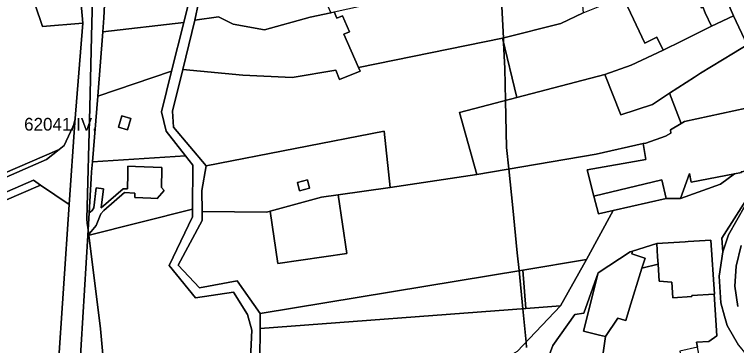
# Model space of a CAD drawing. Extents: x -522079 to -518833, y -1142400 to -1139961.
# Drawn here: x -520623.1 to -520338.9, y -1141173.1 to -1141042.9 of the extents above; entities that cross this region are included whole.
import ezdxf

# ---------------------------------------------------------------- set-up
doc = ezdxf.new("R2010")
doc.units = 0
for name, color, linetype in [('95590013', 7, 'Continuous'), ('95610013', 7, 'Continuous'), ('95620013', 7, 'Continuous'), ('95630013', 7, 'Continuous'), ('95640013', 7, 'Continuous'), ('95660013', 7, 'Continuous')]:
    doc.layers.add(name, color=color, linetype=linetype)

msp = doc.modelspace()

# ---------------------------------------------------------------- linework, layer by layer
at = {"layer": '95590013'}
for points in [[(-520620.51, -1141022.34), (-520648.03, -1140963.9), (-520600.24, -1140966.98), (-520604.67, -1140967.12), (-520604.41, -1140978.31), (-520604.3, -1140983.07), (-520599.81, -1140983.06), (-520599.73, -1140986.18), (-520599.09, -1141003), (-520600.97, -1141003.07), (-520601.06, -1141001.34), (-520601.36, -1141001.34), (-520602.52, -1141000.7), (-520603.99, -1141000.76), (-520605.04, -1141001.54), (-520605.37, -1141001.56), (-520605.29, -1141003.25), (-520607.09, -1141003.32), (-520615.08, -1141003.61), (-520614.42, -1141021.92), (-520598.37, -1141020.83), (-520596.21, -1141046.3), (-520612.04, -1141047.58)], [(-520400.21, -1141032.13), (-520399.24, -1141042.3), (-520408.06, -1141046.45), (-520431.05, -1141052.26), (-520487.67, -1141063.72), (-520493.42, -1141050.65), (-520491.27, -1141049.7), (-520494.03, -1141043.4), (-520496.2, -1141044.35), (-520497.24, -1141041.88), (-520452.37, -1141031.92), (-520412.3, -1141020.92), (-520402.65, -1141017.41), (-520392.22, -1141014.66), (-520391.74, -1141015.46), (-520389.08, -1141019.93), (-520401.32, -1141023.68), (-520401.95, -1141022.11), (-520410.31, -1141025.45), (-520406.62, -1141034.69)], [(-520552.06, -1141045.13), (-520547.82, -1141024.57), (-520531.57, -1141026.89), (-520508.38, -1141020.64), (-520498.56, -1141042.19), (-520506.76, -1141043.95), (-520524.68, -1141048.94), (-520537, -1141046.7), (-520542.8, -1141043.78)], [(-520487.08, -1141065.15), (-520495.15, -1141068.52), (-520496.65, -1141064.79), (-520513.82, -1141067.62), (-520533.21, -1141066.79), (-520556.84, -1141064.48), (-520552.06, -1141045.13), (-520542.8, -1141043.78), (-520537, -1141046.7), (-520524.68, -1141048.94), (-520506.76, -1141043.95), (-520498.56, -1141042.19), (-520497.24, -1141041.88), (-520496.2, -1141044.35), (-520494.03, -1141043.4), (-520491.27, -1141049.7), (-520493.42, -1141050.65), (-520487.67, -1141063.72)], [(-520561.24, -1141065.24), (-520590.32, -1141074.97), (-520588.29, -1141049.68), (-520556.5, -1141046.1)], [(-520487.67, -1141063.72), (-520431.05, -1141052.26), (-520425.4, -1141075.5), (-520447.94, -1141081.43), (-520441.13, -1141105.78), (-520475.18, -1141110.92), (-520477.6, -1141088.85), (-520547.68, -1141102.49), (-520560.53, -1141087.18), (-520560.89, -1141080.93), (-520556.84, -1141064.48), (-520533.21, -1141066.79), (-520513.82, -1141067.62), (-520496.65, -1141064.79), (-520495.15, -1141068.52), (-520487.08, -1141065.15)], [(-520375.66, -1141093.7), (-520394.23, -1141097.85), (-520441.13, -1141105.78), (-520447.94, -1141081.43), (-520425.4, -1141075.5), (-520390.79, -1141066.51), (-520384.48, -1141082.4), (-520371.97, -1141078.27), (-520365.3, -1141073.88), (-520360.71, -1141085.77), (-520364.98, -1141088.31), (-520364.74, -1141089.55), (-520366.94, -1141090.81), (-520374.62, -1141093.47)], [(-520495.67, -1141113.78), (-520502.3, -1141114.71), (-520522.42, -1141120.25), (-520523.74, -1141120.61), (-520549.23, -1141120.44), (-520549.29, -1141112.12), (-520547.68, -1141102.49), (-520477.6, -1141088.85), (-520475.18, -1141110.92)], [(-520492.31, -1141136.96), (-520495.67, -1141113.78), (-520475.18, -1141110.92), (-520441.13, -1141105.78), (-520394.23, -1141097.85), (-520375.66, -1141093.7), (-520374.68, -1141099.98), (-520397.79, -1141103.97), (-520395.09, -1141114.42), (-520393.3, -1141121.36), (-520387.46, -1141120.02), (-520397.97, -1141139.24), (-520423.06, -1141143.4), (-520526.34, -1141160.53), (-520535.5, -1141147.72), (-520550.27, -1141150.4), (-520558.62, -1141141.55), (-520549.21, -1141123.97), (-520549.23, -1141120.44), (-520523.74, -1141120.61), (-520522.42, -1141120.25), (-520519.42, -1141140.9)], [(-520552.84, -1141102.13), (-520552.98, -1141119.42), (-520594.25, -1141129.86), (-520590.98, -1141125.93), (-520589.1, -1141121.25), (-520587.97, -1141120.05), (-520579.73, -1141112.98), (-520575.7, -1141113.22), (-520575.71, -1141114.91), (-520569.44, -1141115.09), (-520566.93, -1141115.3), (-520564.14, -1141112.07), (-520565.25, -1141110.92), (-520565.05, -1141103.74), (-520565.03, -1141103.04), (-520575.39, -1141102.74), (-520578.44, -1141102.51), (-520578.5, -1141105.52), (-520578.63, -1141111.5), (-520580.29, -1141111.47), (-520588.95, -1141118.89), (-520588.02, -1141111.45), (-520590.95, -1141111.08), (-520591.88, -1141118.95), (-520592.5, -1141120.04), (-520593.72, -1141120.93), (-520592.91, -1141107.42), (-520592.76, -1141104.85), (-520592.43, -1141100.83), (-520555.74, -1141098.46)], [(-520345.24, -1141109.63), (-520361.02, -1141115.3), (-520357.5, -1141105.49), (-520356.84, -1141108.9), (-520339.78, -1141105.62)], [(-520506.98, -1141111.26), (-520507.81, -1141107.97), (-520511.72, -1141108.95), (-520510.88, -1141112.27)], [(-520393.3, -1141121.36), (-520395.09, -1141114.42), (-520368.35, -1141107.89), (-520366.58, -1141115.24), (-520387.46, -1141120.02)], [(-520522.42, -1141120.25), (-520502.3, -1141114.71), (-520495.67, -1141113.78), (-520492.31, -1141136.96), (-520519.42, -1141140.9)], [(-520374.94, -1141138.7), (-520375.42, -1141138.55), (-520380.21, -1141137.08), (-520379.87, -1141135.97), (-520370.32, -1141133), (-520369.99, -1141138.16), (-520369.8, -1141141.08), (-520376.18, -1141142.7)], [(-520526.38, -1141166.45), (-520526.34, -1141160.53), (-520423.06, -1141143.4), (-520421.91, -1141158.52)], [(-520392.71, -1141184.99), (-520390.51, -1141169.6), (-520385.67, -1141162.39), (-520383.02, -1141163.15), (-520382.54, -1141163.3), (-520381.05, -1141158.47), (-520376.18, -1141142.7), (-520369.8, -1141141.08), (-520369.36, -1141147.79), (-520364.41, -1141148.17), (-520363.98, -1141154.29), (-520356.57, -1141153.77), (-520356.59, -1141153.47), (-520347.81, -1141152.92), (-520346.65, -1141169.3), (-520349.86, -1141171.48), (-520354.71, -1141171.83), (-520354.34, -1141173.71), (-520361.25, -1141175.35), (-520360.34, -1141179.18), (-520366.93, -1141180.34), (-520378.86, -1141182.41)], [(-520417.36, -1141189.63), (-520411.3, -1141173.03), (-520402.63, -1141160.92), (-520399.1, -1141160.34), (-520393.37, -1141144.49), (-520399.12, -1141167.44), (-520392.92, -1141168.99), (-520390.51, -1141169.6), (-520392.71, -1141184.99)]]:
    msp.add_lwpolyline(points, close=True, dxfattribs=at)
at = {"layer": '95610013'}
for points in [[(-520679.92, -1141124.76), (-520699.09, -1140943.92), (-520632.04, -1140920.85), (-520634.37, -1140902.81), (-520641.23, -1140863.72), (-520646.19, -1140843.58), (-520650.7, -1140826.31), (-520634.79, -1140817.77), (-520621.9, -1140866.86), (-520618.56, -1140880.81), (-520614.37, -1140907.34), (-520612.5, -1140933.48), (-520590.36, -1140946.34), (-520594.75, -1140964.79), (-520649.51, -1140960.76), (-520648.03, -1140963.9), (-520620.51, -1141022.34), (-520612.04, -1141047.58), (-520596.21, -1141046.3), (-520599.33, -1141085.41), (-520603.47, -1141094.45), (-520605.48, -1141096), (-520676.95, -1141126.77)], [(-520586.99, -1141025.98), (-520551.07, -1141024.16), (-520556.5, -1141046.1), (-520588.29, -1141049.68), (-520587.85, -1141044.25)], [(-520565.18, -1141081.15), (-520563.4, -1141088.78), (-520555.74, -1141098.46), (-520592.43, -1141100.83), (-520590.32, -1141074.97), (-520561.24, -1141065.24)], [(-520582.09, -1141087.24), (-520578.55, -1141088.26), (-520577.31, -1141083.78), (-520580.82, -1141082.81)], [(-520597.46, -1141183.55), (-520594.25, -1141129.86), (-520552.98, -1141119.42), (-520553, -1141122.43), (-520562.26, -1141141.67), (-520551.87, -1141154.33), (-520536.94, -1141152.14), (-520531.44, -1141160.96), (-520529.73, -1141167.05), (-520530.26, -1141178.39), (-520534.49, -1141178.34), (-520588.63, -1141182.42)], [(-520432.59, -1141179.7), (-520440.68, -1141181.04), (-520523.78, -1141178.47), (-520526.48, -1141178.44), (-520526.38, -1141166.45), (-520421.91, -1141158.52), (-520408.18, -1141157.48), (-520425.27, -1141175.41)]]:
    msp.add_lwpolyline(points, close=True, dxfattribs=at)
at = {"layer": '95620013'}
msp.add_lwpolyline([(-520607.02, -1141187.64), (-520665.65, -1141273.94), (-520677.78, -1141138.02), (-520612.8, -1141110.04), (-520601.54, -1141117.64), (-520606.07, -1141183.78)], close=True, dxfattribs=at)
at = {"layer": '95630013'}
for points in [[(-520530.26, -1141178.39), (-520529.73, -1141167.05), (-520531.44, -1141160.96), (-520536.94, -1141152.14), (-520551.87, -1141154.33), (-520562.26, -1141141.67), (-520553, -1141122.43), (-520552.98, -1141119.42), (-520552.84, -1141102.13), (-520555.74, -1141098.46), (-520563.4, -1141088.78), (-520565.18, -1141081.15), (-520561.24, -1141065.24), (-520556.5, -1141046.1), (-520551.07, -1141024.16)], [(-520547.82, -1141024.57), (-520552.06, -1141045.13), (-520556.84, -1141064.48), (-520560.89, -1141080.93), (-520560.53, -1141087.18), (-520547.68, -1141102.49), (-520549.29, -1141112.12), (-520549.23, -1141120.44), (-520549.21, -1141123.97), (-520558.62, -1141141.55), (-520550.27, -1141150.4), (-520535.5, -1141147.72), (-520526.34, -1141160.53), (-520526.38, -1141166.45), (-520526.48, -1141178.44)]]:
    msp.add_lwpolyline(points, dxfattribs=at)
at = {"layer": '95640013'}
for points in [[(-520334.74, -1141054.84), (-520340.18, -1141043.47), (-520343.25, -1141036.1), (-520347.88, -1141025.34), (-520350.1, -1141020.17), (-520349.61, -1141019.9), (-520359.98, -1141000.07), (-520369.44, -1140980.74), (-520376.07, -1140958.44), (-520381.51, -1140937.64), (-520383.27, -1140930.85), (-520385, -1140920.46), (-520387.91, -1140902.86), (-520388.38, -1140878.81), (-520385.81, -1140848.46), (-520386.02, -1140848.4), (-520386.88, -1140823.39), (-520383.07, -1140848.38), (-520382.78, -1140878.64), (-520380.96, -1140902.07), (-520377.25, -1140930.57), (-520371.53, -1140953.82), (-520335.76, -1141038.73)], [(-520606.07, -1141183.78), (-520601.54, -1141117.64), (-520599.33, -1141085.41), (-520596.21, -1141046.3), (-520598.37, -1141020.83)], [(-520586.99, -1141025.98), (-520587.85, -1141044.25), (-520588.29, -1141049.68), (-520590.32, -1141074.97), (-520592.43, -1141100.83), (-520592.76, -1141104.85), (-520592.91, -1141107.42), (-520593.72, -1141120.93), (-520594.25, -1141129.86), (-520597.46, -1141183.55)], [(-521027.41, -1141281.92), (-520897.83, -1141225.78), (-520885.55, -1141220.5), (-520708.05, -1141142.54), (-520688.68, -1141134.03), (-520675.02, -1141128.07), (-520610.52, -1141099.9), (-520605.48, -1141096), (-520603.47, -1141094.45), (-520599.33, -1141085.41), (-520601.54, -1141117.64), (-520612.8, -1141110.04), (-520615.64, -1141108.13), (-520683.34, -1141137.56), (-520705.75, -1141147.3), (-520882.39, -1141224.1), (-520895.38, -1141229.74), (-521025.25, -1141286.2)], [(-520425.27, -1141175.41), (-520408.18, -1141157.48), (-520397.97, -1141139.24), (-520387.46, -1141120.02), (-520366.58, -1141115.24), (-520361.02, -1141115.3), (-520345.24, -1141109.63), (-520339.78, -1141105.62), (-520337.04, -1141105.09), (-520337.09, -1141104.85), (-520328.09, -1141103.27), (-520327.42, -1141103.8), (-520344.78, -1141130.88), (-520344.38, -1141136.25), (-520345.84, -1141145.82), (-520345.14, -1141156.25), (-520343.69, -1141161.58), (-520342.68, -1141165.24), (-520338.22, -1141172.95), (-520335.19, -1141176.69)], [(-520335.59, -1141118), (-520342.14, -1141129.51), (-520344.38, -1141136.25), (-520344.78, -1141130.88), (-520327.42, -1141103.8)], [(-520338.22, -1141172.95), (-520342.68, -1141165.24), (-520343.69, -1141161.58), (-520345.14, -1141156.25), (-520345.84, -1141145.82), (-520344.38, -1141136.25), (-520342.14, -1141129.51), (-520335.59, -1141118)], [(-520337.15, -1141133.73), (-520339.09, -1141141.84), (-520339.64, -1141149.76), (-520338.41, -1141157.75)], [(-520338.41, -1141157.75), (-520339.64, -1141149.76), (-520339.09, -1141141.84), (-520337.15, -1141133.73)]]:
    msp.add_lwpolyline(points, dxfattribs=at)
for points in [[(-520367.77, -1141056.92), (-520370.31, -1141051.82), (-520375, -1141054.13), (-520382.96, -1141037.48), (-520379.56, -1141036.01), (-520380, -1141035.01), (-520357.91, -1141024.53), (-520350.1, -1141020.17), (-520347.88, -1141025.34), (-520357.55, -1141029.54), (-520352.93, -1141040.25), (-520352.22, -1141039.94), (-520351.25, -1141042.23), (-520348.84, -1141047.55), (-520360.31, -1141053.23)], [(-520375, -1141054.13), (-520370.31, -1141051.82), (-520367.77, -1141056.92), (-520380.42, -1141062.83), (-520390.79, -1141066.51), (-520425.4, -1141075.5), (-520431.05, -1141052.26), (-520408.06, -1141046.45), (-520399.24, -1141042.3), (-520385.48, -1141036.63), (-520380.26, -1141034.58), (-520380, -1141035.01), (-520379.56, -1141036.01), (-520382.96, -1141037.48)], [(-520352.22, -1141039.94), (-520343.25, -1141036.1), (-520340.18, -1141043.47), (-520348.84, -1141047.55), (-520351.25, -1141042.23)], [(-520348.84, -1141047.55), (-520340.18, -1141043.47), (-520334.74, -1141054.84), (-520340.14, -1141058.06), (-520353.1, -1141065.99), (-520355.55, -1141067.49), (-520365.3, -1141073.88), (-520371.97, -1141078.27), (-520384.48, -1141082.4), (-520390.79, -1141066.51), (-520380.42, -1141062.83), (-520367.77, -1141056.92), (-520360.31, -1141053.23)], [(-520334.74, -1141054.84), (-520329.51, -1141066.36), (-520330.22, -1141066.74), (-520330.35, -1141078.64), (-520359.41, -1141084.99), (-520360.71, -1141085.77), (-520365.3, -1141073.88), (-520355.55, -1141067.49), (-520353.1, -1141065.99), (-520340.14, -1141058.06)], [(-520374.68, -1141099.98), (-520375.66, -1141093.7), (-520374.62, -1141093.47), (-520366.94, -1141090.81), (-520364.74, -1141089.55), (-520364.98, -1141088.31), (-520360.71, -1141085.77), (-520359.41, -1141084.99), (-520330.35, -1141078.64), (-520328.09, -1141103.27), (-520337.09, -1141104.85), (-520337.04, -1141105.09), (-520339.78, -1141105.62), (-520356.84, -1141108.9), (-520357.5, -1141105.49), (-520361.02, -1141115.3), (-520366.58, -1141115.24), (-520368.35, -1141107.89), (-520395.09, -1141114.42), (-520397.79, -1141103.97)], [(-520582.09, -1141087.24), (-520580.82, -1141082.81), (-520577.31, -1141083.78), (-520578.55, -1141088.26)], [(-520676.95, -1141126.77), (-520605.48, -1141096), (-520610.52, -1141099.9), (-520675.02, -1141128.07)], [(-520565.25, -1141110.92), (-520564.14, -1141112.07), (-520566.93, -1141115.3), (-520569.44, -1141115.09), (-520575.71, -1141114.91), (-520575.7, -1141113.22), (-520579.73, -1141112.98), (-520587.97, -1141120.05), (-520589.1, -1141121.25), (-520590.98, -1141125.93), (-520594.25, -1141129.86), (-520593.72, -1141120.93), (-520592.5, -1141120.04), (-520591.88, -1141118.95), (-520590.95, -1141111.08), (-520588.02, -1141111.45), (-520588.95, -1141118.89), (-520580.29, -1141111.47), (-520578.63, -1141111.5), (-520578.5, -1141105.52), (-520578.44, -1141102.51), (-520575.39, -1141102.74), (-520565.03, -1141103.04), (-520565.05, -1141103.74)], [(-520615.64, -1141108.13), (-520612.8, -1141110.04), (-520677.78, -1141138.02), (-520683.09, -1141140.3), (-520683.34, -1141137.56)], [(-520510.88, -1141112.27), (-520511.72, -1141108.95), (-520507.81, -1141107.97), (-520506.98, -1141111.26)], [(-520417.36, -1141189.63), (-520392.71, -1141184.99), (-520378.86, -1141182.41), (-520366.93, -1141180.34), (-520360.34, -1141179.18), (-520353.47, -1141177.71), (-520354.34, -1141173.71), (-520354.71, -1141171.83), (-520349.86, -1141171.48), (-520346.65, -1141169.3), (-520347.81, -1141152.92), (-520347.61, -1141152.91), (-520349.11, -1141131.64), (-520357.95, -1141132.21), (-520359.15, -1141132.28), (-520370.32, -1141133), (-520379.87, -1141135.97), (-520380.82, -1141136.27), (-520393.37, -1141144.49), (-520399.1, -1141160.34), (-520402.63, -1141160.92), (-520411.3, -1141173.03)], [(-520357.95, -1141132.21), (-520349.11, -1141131.64), (-520347.61, -1141152.91), (-520347.81, -1141152.92), (-520356.59, -1141153.47), (-520356.57, -1141153.77), (-520363.98, -1141154.29), (-520364.41, -1141148.17), (-520369.36, -1141147.79), (-520369.8, -1141141.08), (-520369.99, -1141138.16), (-520370.32, -1141133), (-520359.15, -1141132.28)], [(-520379.87, -1141135.97), (-520380.21, -1141137.08), (-520375.42, -1141138.55), (-520374.94, -1141138.7), (-520376.18, -1141142.7), (-520381.05, -1141158.47), (-520382.54, -1141163.3), (-520383.02, -1141163.15), (-520385.67, -1141162.39), (-520390.51, -1141169.6), (-520392.92, -1141168.99), (-520399.12, -1141167.44), (-520393.37, -1141144.49), (-520380.82, -1141136.27)], [(-520421.91, -1141158.52), (-520423.06, -1141143.4), (-520397.97, -1141139.24), (-520408.18, -1141157.48)]]:
    msp.add_lwpolyline(points, close=True, dxfattribs=at)
at = {"layer": '95660013'}
for points in [[(-520627.56, -1140949.7), (-520621.19, -1140951.83), (-520619.9, -1140953.77), (-520618, -1140956.63), (-520614.03, -1140963.37), (-520612.45, -1140966.05), (-520611.1, -1140968.35), (-520603.66, -1140990.19), (-520600.09, -1141003.03), (-520598.92, -1141007.25), (-520592.23, -1141031.31), (-520592.74, -1141051.53), (-520593.45, -1141079.44), (-520594.66, -1141123.3), (-520594.45, -1141124.94), (-520594.12, -1141127.62), (-520593.85, -1141129.76), (-520589.2, -1141166.56), (-520587.79, -1141182.35)], [(-520587.79, -1141182.35), (-520589.2, -1141166.56), (-520593.85, -1141129.76), (-520594.12, -1141127.62), (-520594.45, -1141124.94), (-520594.66, -1141123.3), (-520593.45, -1141079.44), (-520592.74, -1141051.53), (-520592.23, -1141031.31)], [(-520421.57, -1141173.87), (-520421.78, -1141171.75), (-520423.07, -1141158.61), (-520424.53, -1141143.64), (-520425.21, -1141136.71), (-520427.04, -1141118.9), (-520428.61, -1141103.66), (-520429.47, -1141095.28), (-520429.83, -1141076.67), (-520430.07, -1141064.2), (-520430.6, -1141054.09), (-520430.7, -1141052.17), (-520431.36, -1141039.71)], [(-520431.36, -1141039.71), (-520430.7, -1141052.17), (-520430.6, -1141054.09), (-520430.07, -1141064.2), (-520429.83, -1141076.67), (-520429.47, -1141095.28), (-520428.61, -1141103.66), (-520427.04, -1141118.9), (-520425.21, -1141136.71), (-520424.53, -1141143.64), (-520423.07, -1141158.61), (-520421.78, -1141171.75), (-520421.57, -1141173.87)]]:
    msp.add_lwpolyline(points, dxfattribs=at)

# ---------------------------------------------------------------- texts
msp.add_text('62041/IV.', height=5, rotation=0, dxfattribs=at).set_placement((-520619.28, -1141088.57))

doc.saveas('drawing.dxf')
